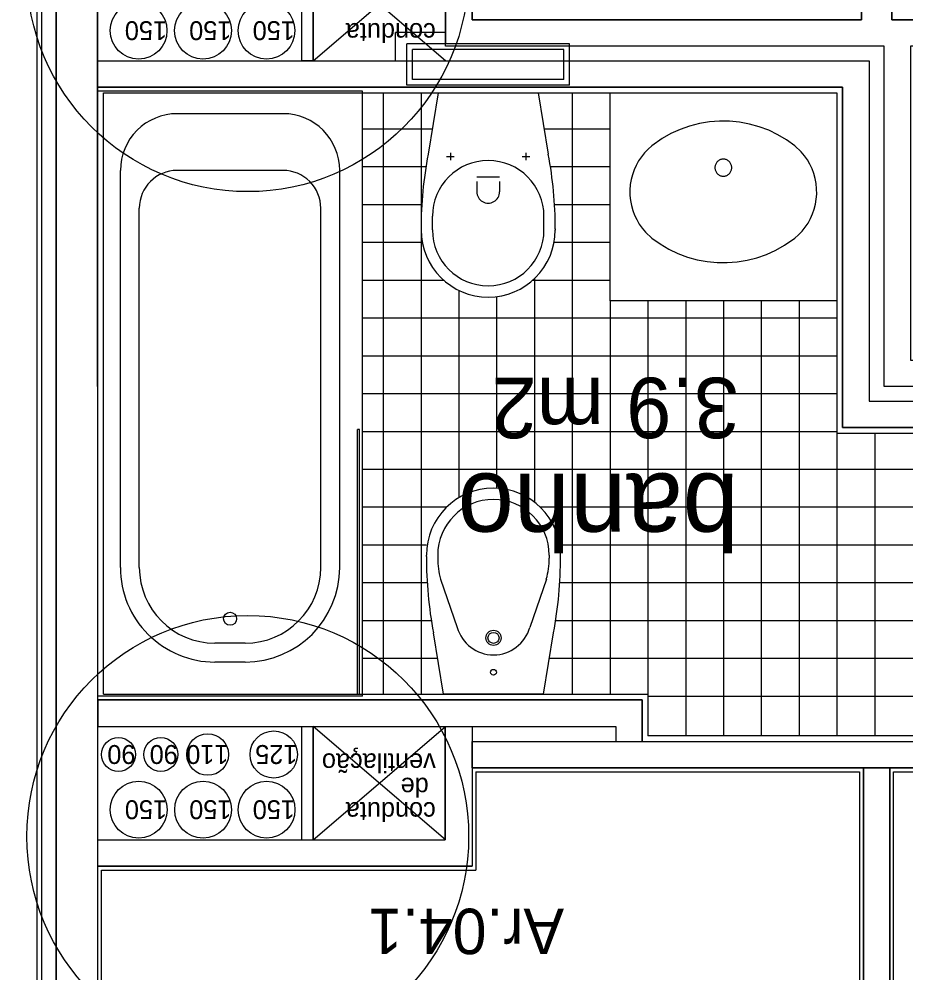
# Model space of a CAD drawing. Extents: x 1278 to 1356, y -253.7 to -224.
# Drawn here: x 1323.824 to 1326.169, y -240.956 to -238.434 of the extents above; entities that cross this region are included whole.
import ezdxf

# ---------------------------------------------------------------- set-up
doc = ezdxf.new("R2010")
doc.units = 0
for name, color, linetype in [('Level 1', 7, 'Continuous'), ('Level 10', 7, 'Continuous'), ('Level 11', 7, 'Continuous'), ('Level 2', 7, 'Continuous'), ('Level 36', 7, 'Continuous'), ('Level 40', 7, 'Continuous'), ('Level 41', 7, 'Continuous'), ('Level 60', 7, 'Continuous'), ('Level 65', 7, 'Continuous'), ('Level 66', 7, 'Continuous'), ('Level 67', 7, 'Continuous'), ('Level 69', 7, 'Continuous'), ('Level 70', 7, 'Continuous')]:
    doc.layers.add(name, color=color, linetype=linetype)

msp = doc.modelspace()

# ---------------------------------------------------------------- linework, layer by layer
at = {"layer": 'Level 1'}
for p, q in [((1324.0318, -242.039), (1324.0317, -232.2657)), ((1326.0518, -236.6557), (1326.0518, -238.4357)), ((1326.1318, -238.4357), (1326.1318, -236.6557)), ((1323.871, -236.7713), (1323.871, -242.1713)), ((1323.9218, -242.1713), (1323.9218, -236.7713)), ((1324.5717, -238.544), (1324.5717, -238.244)), ((1324.6017, -238.544), (1324.6017, -238.244)), ((1326.0518, -238.4357), (1325.0225, -238.4357)), ((1326.2168, -238.4357), (1326.1318, -238.4357)), ((1324.9517, -238.469), (1324.8194, -238.469)), ((1324.9517, -238.499), (1324.8494, -238.499)), ((1326.1118, -238.5057), (1324.9517, -238.5057)), ((1326.1118, -239.4057), (1326.1118, -238.5057)), ((1324.0318, -238.544), (1326.0718, -238.544)), ((1326.0718, -238.544), (1326.0718, -239.444)), ((1324.0318, -238.614), (1326.0018, -238.614)), ((1326.0018, -238.614), (1326.0018, -239.514)), ((1327.1118, -239.4057), (1326.1118, -239.4057)), ((1326.0718, -239.444), (1327.0718, -239.444)), ((1326.0018, -239.514), (1327.0018, -239.514)), ((1324.0318, -240.234), (1325.4718, -240.234)), ((1325.4718, -240.234), (1325.4718, -240.344)), ((1324.0318, -240.304), (1324.951, -240.304)), ((1324.5718, -240.604), (1324.5718, -240.304)), ((1324.6018, -240.604), (1324.6018, -240.304)), ((1325.0218, -240.304), (1325.4018, -240.304)), ((1325.4018, -240.304), (1325.4018, -240.344)), ((1325.0218, -240.414), (1326.0568, -240.414)), ((1326.0568, -240.414), (1326.0568, -242.194)), ((1326.1268, -242.194), (1326.1268, -240.414)), ((1326.1268, -240.414), (1326.2368, -240.414)), ((1324.0318, -240.6039), (1324.951, -240.6039)), ((1324.031, -240.6739), (1325.0218, -240.6739))]:
    msp.add_line(p, q, dxfattribs=at)
for points in [[(1325.0225, -238.4357), (1325.0225, -238.174)], [(1324.9517, -238.244), (1324.9517, -238.499)], [(1324.951, -240.304), (1324.951, -240.604)], [(1325.0218, -240.304), (1325.0218, -240.344)], [(1325.0218, -240.414), (1325.0218, -240.674)]]:
    msp.add_lwpolyline(points, dxfattribs=at)
at = {"layer": 'Level 10'}
for p, q in [((1324.7868, -238.629), (1324.7868, -240.219)), ((1324.8868, -238.629), (1324.8868, -240.219)), ((1325.2868, -238.629), (1325.2868, -240.219)), ((1324.7318, -238.724), (1324.9165, -238.724)), ((1325.2124, -238.724), (1325.3868, -238.724)), ((1324.7318, -238.824), (1324.8998, -238.824)), ((1325.2291, -238.824), (1325.3868, -238.824)), ((1324.7318, -238.924), (1324.8889, -238.924)), ((1325.24, -238.924), (1325.3868, -238.924)), ((1324.7318, -239.024), (1324.89, -239.024)), ((1325.239, -239.024), (1325.3868, -239.024)), ((1324.7318, -239.124), (1324.9463, -239.124)), ((1325.1826, -239.124), (1325.3868, -239.124)), ((1325.1868, -239.1201), (1325.1868, -239.7109)), ((1324.9868, -239.1511), (1324.9868, -239.6995)), ((1325.0868, -239.1676), (1325.0868, -239.6742)), ((1325.3868, -239.179), (1325.3868, -240.219)), ((1325.4868, -239.179), (1325.4868, -240.219)), ((1325.5868, -239.179), (1325.5868, -240.329)), ((1325.6868, -239.179), (1325.6868, -240.329)), ((1325.7868, -239.179), (1325.7868, -240.329)), ((1325.8868, -239.179), (1325.8868, -240.329)), ((1324.7318, -239.224), (1325.9868, -239.224)), ((1324.7318, -239.324), (1325.9868, -239.324)), ((1324.7318, -239.424), (1325.9868, -239.424)), ((1324.7318, -239.524), (1325.9868, -239.524)), ((1325.9868, -239.529), (1325.9868, -240.329)), ((1326.0868, -239.529), (1326.0868, -240.329)), ((1324.7318, -239.624), (1326.9868, -239.624)), ((1324.7318, -239.724), (1324.955, -239.724)), ((1325.2019, -239.724), (1326.9868, -239.724)), ((1324.7318, -239.824), (1324.9012, -239.824)), ((1325.2555, -239.824), (1326.8968, -239.824)), ((1324.7318, -239.924), (1324.9031, -239.924)), ((1325.2538, -239.924), (1326.8968, -239.924)), ((1324.7318, -240.024), (1324.9139, -240.024)), ((1325.243, -240.024), (1326.8968, -240.024)), ((1324.7318, -240.124), (1324.9305, -240.124)), ((1325.2264, -240.124), (1326.8968, -240.124)), ((1325.4868, -240.224), (1326.8968, -240.224))]:
    msp.add_line(p, q, dxfattribs=at)
at = {"layer": 'Level 11'}
for p, q in [((1324.8494, -238.609), (1324.8494, -238.499)), ((1325.2794, -238.499), (1324.8494, -238.499)), ((1325.2794, -238.609), (1325.2794, -238.499)), ((1325.2644, -238.514), (1324.8644, -238.514)), ((1324.8644, -238.594), (1324.8644, -238.514)), ((1325.2644, -238.594), (1325.2644, -238.514)), ((1325.2644, -238.594), (1324.8644, -238.594)), ((1324.7318, -238.624), (1324.0318, -238.624)), ((1324.0318, -240.224), (1324.0318, -238.624)), ((1324.0318, -240.229), (1324.0318, -238.629)), ((1324.7318, -240.224), (1324.7318, -238.624)), ((1325.2794, -238.609), (1324.8494, -238.609)), ((1324.9321, -238.629), (1324.9055, -238.791)), ((1324.9321, -238.629), (1325.1968, -238.629)), ((1325.1968, -238.629), (1325.2234, -238.791)), ((1324.5218, -238.684), (1324.2418, -238.684)), ((1325.6762, -238.7034), (1325.6496, -238.7055)), ((1325.7029, -238.7037), (1325.6762, -238.7034)), ((1325.7294, -238.7063), (1325.7029, -238.7037)), ((1325.5721, -238.7256), (1325.5478, -238.7367)), ((1325.5973, -238.7166), (1325.5721, -238.7256)), ((1325.6231, -238.7099), (1325.5973, -238.7166)), ((1325.6496, -238.7055), (1325.6231, -238.7099)), ((1325.7556, -238.7113), (1325.7294, -238.7063)), ((1325.7815, -238.7185), (1325.7556, -238.7113)), ((1325.8065, -238.728), (1325.7815, -238.7185)), ((1325.8305, -238.7397), (1325.8065, -238.728)), ((1325.5246, -238.75), (1325.4975, -238.7691)), ((1325.5478, -238.7367), (1325.5246, -238.75)), ((1325.8535, -238.7534), (1325.8305, -238.7397)), ((1325.8752, -238.7691), (1325.8535, -238.7534)), ((1325.4875, -238.7779), (1325.4782, -238.7874)), ((1325.4975, -238.7691), (1325.4875, -238.7779)), ((1325.8924, -238.7851), (1325.8752, -238.7691)), ((1324.9544, -238.7972), (1324.9744, -238.7972)), ((1324.9644, -238.7872), (1324.9644, -238.8072)), ((1325.1544, -238.7972), (1325.1744, -238.7972)), ((1325.1644, -238.7872), (1325.1644, -238.8072)), ((1325.4698, -238.7978), (1325.4623, -238.8089)), ((1325.4782, -238.7874), (1325.4698, -238.7978)), ((1325.6787, -238.8055), (1325.6769, -238.8063)), ((1325.6806, -238.8049), (1325.6787, -238.8055)), ((1325.6825, -238.8045), (1325.6806, -238.8049)), ((1325.6844, -238.8043), (1325.6825, -238.8045)), ((1325.6863, -238.8042), (1325.6844, -238.8043)), ((1325.6883, -238.8043), (1325.6863, -238.8042)), ((1325.6902, -238.8045), (1325.6883, -238.8043)), ((1325.6921, -238.8049), (1325.6902, -238.8045)), ((1325.694, -238.8055), (1325.6921, -238.8049)), ((1325.6958, -238.8063), (1325.694, -238.8055)), ((1325.901, -238.7953), (1325.8924, -238.7851)), ((1325.9087, -238.8062), (1325.901, -238.7953)), ((1325.4558, -238.8206), (1325.4503, -238.8328)), ((1325.4623, -238.8089), (1325.4558, -238.8206)), ((1325.6641, -238.8248), (1325.664, -238.8267)), ((1325.664, -238.8267), (1325.6641, -238.8287)), ((1325.6644, -238.8228), (1325.6641, -238.8248)), ((1325.6641, -238.8287), (1325.6644, -238.8307)), ((1325.6648, -238.8209), (1325.6644, -238.8228)), ((1325.6644, -238.8307), (1325.6648, -238.8326)), ((1325.6654, -238.819), (1325.6648, -238.8209)), ((1325.6661, -238.8172), (1325.6654, -238.819)), ((1325.667, -238.8155), (1325.6661, -238.8172)), ((1325.6681, -238.8138), (1325.667, -238.8155)), ((1325.6693, -238.8122), (1325.6681, -238.8138)), ((1325.6706, -238.8108), (1325.6693, -238.8122)), ((1325.672, -238.8095), (1325.6706, -238.8108)), ((1325.6736, -238.8083), (1325.672, -238.8095)), ((1325.6752, -238.8072), (1325.6736, -238.8083)), ((1325.6769, -238.8063), (1325.6752, -238.8072)), ((1325.6975, -238.8072), (1325.6958, -238.8063)), ((1325.6991, -238.8083), (1325.6975, -238.8072)), ((1325.7007, -238.8095), (1325.6991, -238.8083)), ((1325.7021, -238.8108), (1325.7007, -238.8095)), ((1325.7034, -238.8122), (1325.7021, -238.8108)), ((1325.7046, -238.8138), (1325.7034, -238.8122)), ((1325.7057, -238.8155), (1325.7046, -238.8138)), ((1325.7066, -238.8172), (1325.7057, -238.8155)), ((1325.7073, -238.819), (1325.7066, -238.8172)), ((1325.7079, -238.8209), (1325.7073, -238.819)), ((1325.7083, -238.8228), (1325.7079, -238.8209)), ((1325.7079, -238.8326), (1325.7083, -238.8307)), ((1325.7086, -238.8248), (1325.7083, -238.8228)), ((1325.7083, -238.8307), (1325.7086, -238.8287)), ((1325.7087, -238.8267), (1325.7086, -238.8248)), ((1325.7086, -238.8287), (1325.7087, -238.8267)), ((1325.9155, -238.8177), (1325.9087, -238.8062)), ((1325.9212, -238.8298), (1325.9155, -238.8177)), ((1325.9259, -238.8424), (1325.9212, -238.8298)), ((1324.0918, -239.884), (1324.0918, -238.834)), ((1324.5218, -238.834), (1324.2418, -238.834)), ((1324.6718, -239.884), (1324.6718, -238.834)), ((1325.0344, -238.8512), (1325.0944, -238.8512)), ((1325.4459, -238.8454), (1325.4426, -238.8584)), ((1325.4503, -238.8328), (1325.4459, -238.8454)), ((1325.6648, -238.8326), (1325.6654, -238.8345)), ((1325.6654, -238.8345), (1325.6661, -238.8363)), ((1325.6661, -238.8363), (1325.667, -238.838)), ((1325.667, -238.838), (1325.6681, -238.8397)), ((1325.6681, -238.8397), (1325.6693, -238.8412)), ((1325.6693, -238.8412), (1325.6706, -238.8427)), ((1325.6706, -238.8427), (1325.672, -238.844)), ((1325.672, -238.844), (1325.6736, -238.8452)), ((1325.6736, -238.8452), (1325.6752, -238.8463)), ((1325.6752, -238.8463), (1325.6769, -238.8472)), ((1325.6769, -238.8472), (1325.6787, -238.8479)), ((1325.6787, -238.8479), (1325.6806, -238.8485)), ((1325.6806, -238.8485), (1325.6825, -238.849)), ((1325.6825, -238.849), (1325.6844, -238.8492)), ((1325.6844, -238.8492), (1325.6863, -238.8493)), ((1325.6863, -238.8493), (1325.6883, -238.8492)), ((1325.6883, -238.8492), (1325.6902, -238.849)), ((1325.6902, -238.849), (1325.6921, -238.8485)), ((1325.6921, -238.8485), (1325.694, -238.8479)), ((1325.694, -238.8479), (1325.6958, -238.8472)), ((1325.6958, -238.8472), (1325.6975, -238.8463)), ((1325.6975, -238.8463), (1325.6991, -238.8452)), ((1325.6991, -238.8452), (1325.7007, -238.844)), ((1325.7007, -238.844), (1325.7021, -238.8427)), ((1325.7021, -238.8427), (1325.7034, -238.8412)), ((1325.7034, -238.8412), (1325.7046, -238.8397)), ((1325.7046, -238.8397), (1325.7057, -238.838)), ((1325.7057, -238.838), (1325.7066, -238.8363)), ((1325.7066, -238.8363), (1325.7073, -238.8345)), ((1325.7073, -238.8345), (1325.7079, -238.8326)), ((1325.9294, -238.8553), (1325.9259, -238.8424)), ((1325.9319, -238.8685), (1325.9294, -238.8553)), ((1325.0344, -238.8635), (1325.0344, -238.8907)), ((1325.0944, -238.8635), (1325.0944, -238.8907)), ((1325.4404, -238.8716), (1325.4394, -238.8863)), ((1325.4426, -238.8584), (1325.4404, -238.8716)), ((1325.9332, -238.8831), (1325.9319, -238.8685)), ((1325.4394, -238.8863), (1325.4395, -238.9001)), ((1325.4395, -238.9001), (1325.4408, -238.9135)), ((1325.9323, -238.9103), (1325.9333, -238.8969)), ((1325.9333, -238.8969), (1325.9332, -238.8831)), ((1325.4408, -238.9135), (1325.4433, -238.9267)), ((1325.4433, -238.9267), (1325.4468, -238.9396)), ((1325.9268, -238.9365), (1325.9301, -238.9235)), ((1325.9301, -238.9235), (1325.9323, -238.9103)), ((1324.1418, -239.884), (1324.1418, -238.934)), ((1324.6218, -239.884), (1324.6218, -238.934)), ((1324.9169, -238.9915), (1324.9169, -238.9554)), ((1325.2119, -238.9915), (1325.2119, -238.9554)), ((1325.4468, -238.9396), (1325.4515, -238.9521)), ((1325.4515, -238.9521), (1325.4572, -238.9642)), ((1325.9169, -238.9614), (1325.9224, -238.9492)), ((1325.9224, -238.9492), (1325.9268, -238.9365)), ((1325.4572, -238.9642), (1325.464, -238.9758)), ((1325.464, -238.9758), (1325.4717, -238.9867)), ((1325.9029, -238.9841), (1325.9104, -238.9731)), ((1325.9104, -238.9731), (1325.9169, -238.9614)), ((1324.887, -238.9881), (1324.8869, -238.9918)), ((1325.2419, -238.9881), (1325.2419, -238.9918)), ((1325.4717, -238.9867), (1325.4803, -238.9969)), ((1325.4803, -238.9969), (1325.4975, -239.0128)), ((1325.8752, -239.0128), (1325.8852, -239.0041)), ((1325.8852, -239.0041), (1325.8945, -238.9945)), ((1325.8945, -238.9945), (1325.9029, -238.9841)), ((1325.4975, -239.0128), (1325.5192, -239.0285)), ((1325.5192, -239.0285), (1325.5422, -239.0422)), ((1325.8249, -239.0452), (1325.8481, -239.032)), ((1325.8481, -239.032), (1325.8752, -239.0128)), ((1325.5422, -239.0422), (1325.5662, -239.0539)), ((1325.5662, -239.0539), (1325.5912, -239.0634)), ((1325.7754, -239.0653), (1325.8006, -239.0564)), ((1325.8006, -239.0564), (1325.8249, -239.0452)), ((1325.5912, -239.0634), (1325.6169, -239.0706)), ((1325.6169, -239.0706), (1325.6433, -239.0746)), ((1325.6433, -239.0746), (1325.6698, -239.0772)), ((1325.6698, -239.0772), (1325.6965, -239.0775)), ((1325.6965, -239.0775), (1325.7231, -239.0754)), ((1325.7231, -239.0754), (1325.7494, -239.071)), ((1325.7494, -239.071), (1325.7754, -239.0653)), ((1324.901, -239.8548), (1324.901, -239.8512)), ((1324.931, -239.8515), (1324.931, -239.8596)), ((1325.226, -239.8515), (1325.226, -239.8596)), ((1325.256, -239.8548), (1325.256, -239.8512)), ((1324.9386, -239.9145), (1324.9823, -240.0424)), ((1325.2183, -239.9145), (1325.1746, -240.0424)), ((1324.9461, -240.219), (1324.9195, -240.0569)), ((1325.2108, -240.219), (1325.2374, -240.0569)), ((1324.4218, -240.084), (1324.3418, -240.084)), ((1324.4218, -240.134), (1324.3418, -240.134)), ((1324.7318, -240.224), (1324.0318, -240.224)), ((1325.2108, -240.219), (1324.9461, -240.219))]:
    msp.add_line(p, q, dxfattribs=at)
for centre, radius in [((1324.3818, -240.0195), 0.0173), ((1325.0785, -240.0701), 0.02), ((1325.0785, -240.0701), 0.0146), ((1325.0784, -240.161), 0.00766)]:
    msp.add_circle(centre, radius, dxfattribs=at)
for centre, radius, start, end in [((1324.2418, -238.834), 0.15, 89.9999, 180.0002), ((1324.5218, -238.834), 0.15, 360, 90), ((1325.0645, -238.9554), 0.1475, 0.0002, 179.9999), ((1324.2418, -238.934), 0.1, 90.0001, 179.9999), ((1324.5218, -238.934), 0.1, 360, 90.0001), ((1325.0645, -238.8905), 0.03, 179.9995, 0.0013), ((1325.0645, -238.9915), 0.1775, 180.0002, 359.9999), ((1325.0645, -238.9915), 0.1475, 180.0002, 359.9999), ((1325.0784, -239.8515), 0.1775, 0.0002, 179.9999), ((1325.0784, -239.8515), 0.1475, 0.0002, 179.9999), ((1325.1309, -239.8596), 0.2, 180.0017, 195.9319), ((1325.0259, -239.8596), 0.2, 344.0693, 0.0006), ((1324.3418, -239.884), 0.25, 180, 270.0001), ((1324.3418, -239.884), 0.2, 180, 270), ((1324.4218, -239.884), 0.25, 269.9999, 359.9999), ((1324.4218, -239.884), 0.2, 270, 0), ((1325.0785, -240.015), 0.1, 195.9317, 344.1953)]:
    msp.add_arc(centre, radius, start, end, dxfattribs=at)
for centre, major_axis, ratio, start_param, end_param in [((1326.287, -238.9881), (-1.4, 0), 0.867931, 6.120269, 6.283188), ((1323.842, -238.9881), (1.4, 0), 0.867931, 6.283184, 6.446103), ((1326.301, -239.8549), (-1.4, 0), 0.88995, 6.283183, 6.446102), ((1323.8559, -239.8549), (1.4, 0), 0.88995, 6.120269, 6.283187)]:
    msp.add_ellipse(centre, major_axis=major_axis, ratio=ratio, start_param=start_param, end_param=end_param, dxfattribs=at)
at = {"layer": 'Level 2'}
for p, q in [((1325.3868, -239.179), (1325.3868, -238.629)), ((1325.9868, -238.629), (1325.9868, -239.179)), ((1325.9868, -239.179), (1325.3868, -239.179))]:
    msp.add_line(p, q, dxfattribs=at)
at = {"layer": 'Level 36'}
for p, q in [((1324.7238, -239.519), (1324.7188, -239.519)), ((1324.7188, -240.219), (1324.7188, -239.519)), ((1324.7238, -240.219), (1324.7238, -239.519))]:
    msp.add_line(p, q, dxfattribs=at)
at = {"layer": 'Level 41'}
for p, q in [((1324.9518, -238.544), (1324.6018, -238.244)), ((1324.6018, -238.544), (1324.9518, -238.244)), ((1324.9518, -240.604), (1324.6018, -240.304)), ((1324.6018, -240.604), (1324.9518, -240.304))]:
    msp.add_line(p, q, dxfattribs=at)
for centre, radius in [((1324.14, -238.4644), 0.075), ((1324.3102, -238.4644), 0.075), ((1324.4782, -238.4644), 0.075), ((1324.4974, -240.3785), 0.0625), ((1324.0866, -240.3785), 0.045), ((1324.1986, -240.3785), 0.045), ((1324.3226, -240.3785), 0.055), ((1324.1401, -240.5244), 0.075), ((1324.3103, -240.5244), 0.075), ((1324.4783, -240.5244), 0.075)]:
    msp.add_circle(centre, radius, dxfattribs=at)
at = {"layer": 'Level 65'}
for p, q in [((1324.0468, -240.219), (1324.0468, -238.629)), ((1324.0468, -238.629), (1325.9868, -238.629)), ((1325.9868, -238.629), (1325.9868, -239.529)), ((1325.9868, -239.529), (1326.9868, -239.529)), ((1324.0468, -240.219), (1325.4868, -240.219)), ((1325.4868, -240.219), (1325.4868, -240.329)), ((1326.2368, -240.329), (1325.4868, -240.329)), ((1325.0318, -240.424), (1326.0468, -240.424)), ((1326.0468, -240.424), (1326.0468, -242.194)), ((1326.1368, -242.194), (1326.1368, -240.424)), ((1326.1368, -240.424), (1326.2368, -240.424)), ((1324.0418, -242.029), (1324.0418, -240.6839)), ((1324.0418, -240.6839), (1325.0318, -240.6839))]:
    msp.add_line(p, q, dxfattribs=at)
msp.add_lwpolyline([(1325.0318, -240.424), (1325.0318, -240.6839)], dxfattribs=at)
at = {"layer": 'Level 66'}
for p, q in [((1324.8194, -238.544), (1324.8194, -238.469)), ((1324.8494, -238.544), (1324.8494, -238.499)), ((1324.9517, -238.5057), (1324.9517, -238.499)), ((1325.0218, -240.344), (1325.4018, -240.344)), ((1325.4718, -240.344), (1326.2368, -240.344))]:
    msp.add_line(p, q, dxfattribs=at)
at = {"layer": 'Level 67'}
for points in [[(1329.2017, -240.234), (1329.2017, -240.304), (1327.1117, -240.304), (1327.1117, -239.4057), (1326.1117, -239.4057), (1326.1117, -238.5057), (1324.9517, -238.5057), (1324.9517, -238.244), (1324.0317, -238.244), (1324.0317, -238.174), (1325.0225, -238.174), (1325.0225, -238.4357), (1326.0517, -238.4357), (1326.0517, -236.6557), (1326.1317, -236.6557), (1326.1317, -238.4357), (1326.2205, -238.4357), (1326.2167, -238.4357), (1326.2167, -238.5057), (1326.1817, -238.5057), (1326.1817, -239.3357), (1327.1817, -239.3357), (1327.1817, -240.234), (1329.2017, -240.234)], [(1323.871, -242.1713), (1323.801, -242.1713), (1323.801, -236.7713), (1323.871, -236.7713), (1323.871, -242.1713)], [(1324.031, -242.1713), (1324.0318, -242.1713), (1324.0318, -242.109), (1324.6318, -242.109), (1324.6318, -242.039), (1324.0318, -242.039), (1324.031, -236.7713), (1323.9218, -236.7713), (1323.9218, -242.1713), (1324.0318, -242.1713)], [(1324.6017, -238.244), (1324.6017, -238.544), (1324.5717, -238.544), (1324.5717, -238.244)], [(1329.2018, -240.414), (1326.9668, -240.414), (1326.9668, -240.334), (1327.0018, -240.334), (1327.0018, -239.514), (1326.0018, -239.514), (1326.0018, -238.614), (1324.0317, -238.614), (1324.0318, -238.544), (1326.0718, -238.544), (1326.0718, -239.444), (1327.0718, -239.444), (1327.0718, -240.344), (1329.2018, -240.344)], [(1325.4718, -240.344), (1325.4718, -240.234), (1324.0318, -240.234), (1324.0318, -240.304), (1325.4018, -240.304), (1325.4018, -240.344)], [(1325.0218, -240.304), (1325.0218, -240.674), (1324.0318, -240.674), (1324.0318, -240.604), (1324.5718, -240.604), (1324.5718, -240.304), (1324.6018, -240.304), (1324.6018, -240.604), (1324.951, -240.604), (1324.951, -240.304)], [(1326.2368, -240.414), (1325.0218, -240.414), (1325.0218, -240.344), (1326.2368, -240.344)], [(1326.1268, -240.414), (1326.1268, -242.194), (1326.0568, -242.194), (1326.0568, -240.414)]]:
    msp.add_lwpolyline(points, close=True, dxfattribs=at)
at = {"layer": 'Level 69'}
for centre in [(1324.4285, -238.3059), (1324.4286, -240.5951), (1324.4286, -240.5951)]:
    msp.add_circle(centre, 0.5842, dxfattribs=at)
at = {"layer": 'Level 70'}
msp.add_line((1323.884, -250.7923), (1323.884, -229.6198), dxfattribs=at)

# ---------------------------------------------------------------- texts
at = {"layer": 'Level 40'}
msp.add_text('Ar.04.1', height=0.12, rotation=180, dxfattribs=at).set_placement((1325.265, -240.7863))
at = {"layer": 'Level 41'}
for s, p in [('150', (1324.215, -238.4394)), ('150', (1324.3852, -238.4394)), ('150', (1324.5532, -238.4394)), ('conduta', (1324.9258, -238.4444)), ('90', (1324.1316, -240.3535)), ('90', (1324.2436, -240.3535)), ('110', (1324.3776, -240.3535)), ('125', (1324.5599, -240.3535)), ('ventilação ', (1324.9258, -240.3755)), (' de ', (1324.9258, -240.4399)), ('150', (1324.2151, -240.4994)), ('150', (1324.3853, -240.4994)), ('150', (1324.5533, -240.4994)), ('conduta', (1324.9258, -240.5044))]:
    msp.add_text(s, height=0.05, rotation=180, dxfattribs=at).set_placement(p)
at = {"layer": 'Level 60'}
for s, height, p in [('3.9 m2', 0.16, (1325.7277, -239.3821)), ('banho', 0.2, (1325.7275, -239.6356))]:
    msp.add_text(s, height=height, rotation=180, dxfattribs=at).set_placement(p)

doc.saveas('drawing.dxf')
